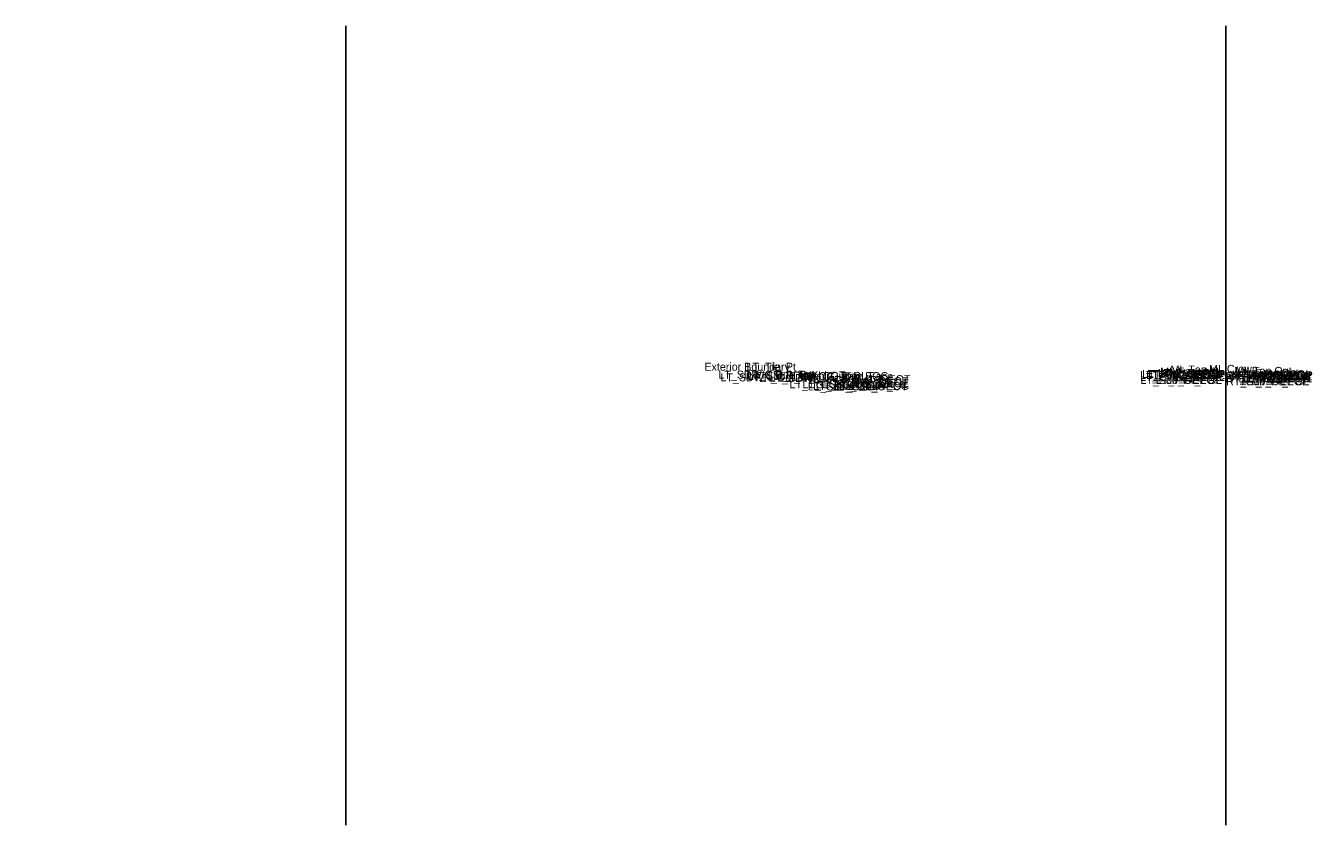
# Model space of a CAD drawing. Extents: x 0 to 6300, y -50 to 9550.
# Drawn here: x 3000 to 3160.8, y 7450 to 7550 of the extents above; entities that cross this region are included whole.
import ezdxf

# ---------------------------------------------------------------- set-up
doc = ezdxf.new("R2010")
doc.units = 0
for name, color, linetype in [('Default', 7, 'Continuous'), ('Prop XS Exc Vertical Line 1', 7, 'Continuous'), ('Prop XS Exc Vertical Line 2', 7, 'Continuous')]:
    doc.layers.add(name, color=color, linetype=linetype)

msp = doc.modelspace()

# ---------------------------------------------------------------- linework, layer by layer
at = {"layer": 'Prop XS Exc Vertical Line 1'}
msp.add_line((3040, 7550), (3040, 7450), dxfattribs=at)
at = {"layer": 'Prop XS Exc Vertical Line 2'}
msp.add_line((3150, 7550), (3150, 7450), dxfattribs=at)

# ---------------------------------------------------------------- texts
at = {"layer": 'Default'}
for s, height, p in [('Exterior Boundary', 1, (3084.83, 7506.85)), ('LT_Tie_Pt', 1, (3090.11, 7506.85)), ('LT_PV1_OEEOP', 1, (3139.53, 7505.94)), ('LT_PV1_IEEOP', 1, (3140.29, 7505.94)), ('LT_PV1_PGL', 1, (3141.51, 7506.07)), ('MI_Face In', 1, (3141.81, 7506.24)), ('MI_Bot In', 1, (3142.98, 7506.07)), ('MI_Top In', 1, (3143.1, 7506.49)), ('MI_Crown', 1, (3147.91, 7506.58)), ('MI_Top Out', 1, (3151.18, 7506.33)), ('MI_Face Out', 1, (3151.39, 7506.08)), ('RT_PV1_PGL', 1, (3152.22, 7505.91)), ('MI_Bot Out', 1, (3152.58, 7505.91)), ('LT_SDWK_Out_Top', 1, (3086.58, 7505.86)), ('LT_SDWK_Out_Bot', 1, (3086.83, 7505.53)), ('LT_CSLP_Pnt', 1, (3090.1, 7505.86)), ('LT_Sub_Trench_Out_DLT', 1, (3090.23, 7505.71)), ('LT_SDWK_In_Top', 1, (3092.74, 7505.76)), ('LT_SDWK_In_Bot', 1, (3092.99, 7505.43)), ('LT_CG1_Shelf_Out', 1, (3095.48, 7504.65)), ('LT_CG_Top_BOC', 1, (3096.81, 7505.67)), ('LT_CG_Bot_BOC', 1, (3097.09, 7504.66)), ('LT_CG_Top_Face', 1, (3097.34, 7505.67)), ('LT_Sub_OEOP', 1, (3097.77, 7504.39)), ('LT_CG_Top_Gut', 1, (3097.87, 7505.17)), ('LT_Sub_OEOT_CG', 1, (3098.44, 7504.46)), ('LT_PV2_OEOT', 1, (3100.99, 7505.04)), ('LT_PV3_OEOT', 1, (3100.99, 7504.79)), ('LT_Sub_OEOT', 1, (3101.04, 7504.41)), ('LT_PV1_OEOT', 1, (3101.23, 7505.29)), ('LT_CG_Bot_IE', 1, (3101.34, 7504.71)), ('LT_PV2_OEEOP', 1, (3139.29, 7505.82)), ('LT_PV3_OEEOP', 1, (3139.29, 7505.57)), ('LT_Sub_OEEOP', 1, (3139.34, 7505.19)), ('LT_PV2_IEEOP', 1, (3140.05, 7505.82)), ('LT_PV2_PGL1', 1, (3140.89, 7505.82)), ('LT_PV3_PGL1', 1, (3140.89, 7505.57)), ('LT_PV2_PGL', 1, (3141.27, 7505.82)), ('LT_PV4_PGL', 1, (3141.27, 7505.19)), ('RT_PV2_OEEOP', 1, (3150, 7505.66)), ('RT_PV3_OEEOP', 1, (3150, 7505.41)), ('RT_Sub_OEEOP', 1, (3150.05, 7505.04)), ('RT_PV1_OEEOP', 1, (3150.24, 7505.79)), ('RT_PV2_IEEOP', 1, (3150.76, 7505.66)), ('RT_PV1_IEEOP', 1, (3151, 7505.79)), ('RT_PV2_PGL1', 1, (3151.6, 7505.66)), ('RT_PV3_PGL1', 1, (3151.6, 7505.41)), ('RT_PV2_PGL', 1, (3151.98, 7505.66)), ('RT_PV4_PGL', 1, (3151.98, 7505.04)), ('-', 0.0001, (3000, 7500))]:
    msp.add_text(s, height=height, dxfattribs=at).set_placement(p)

doc.saveas('drawing.dxf')
